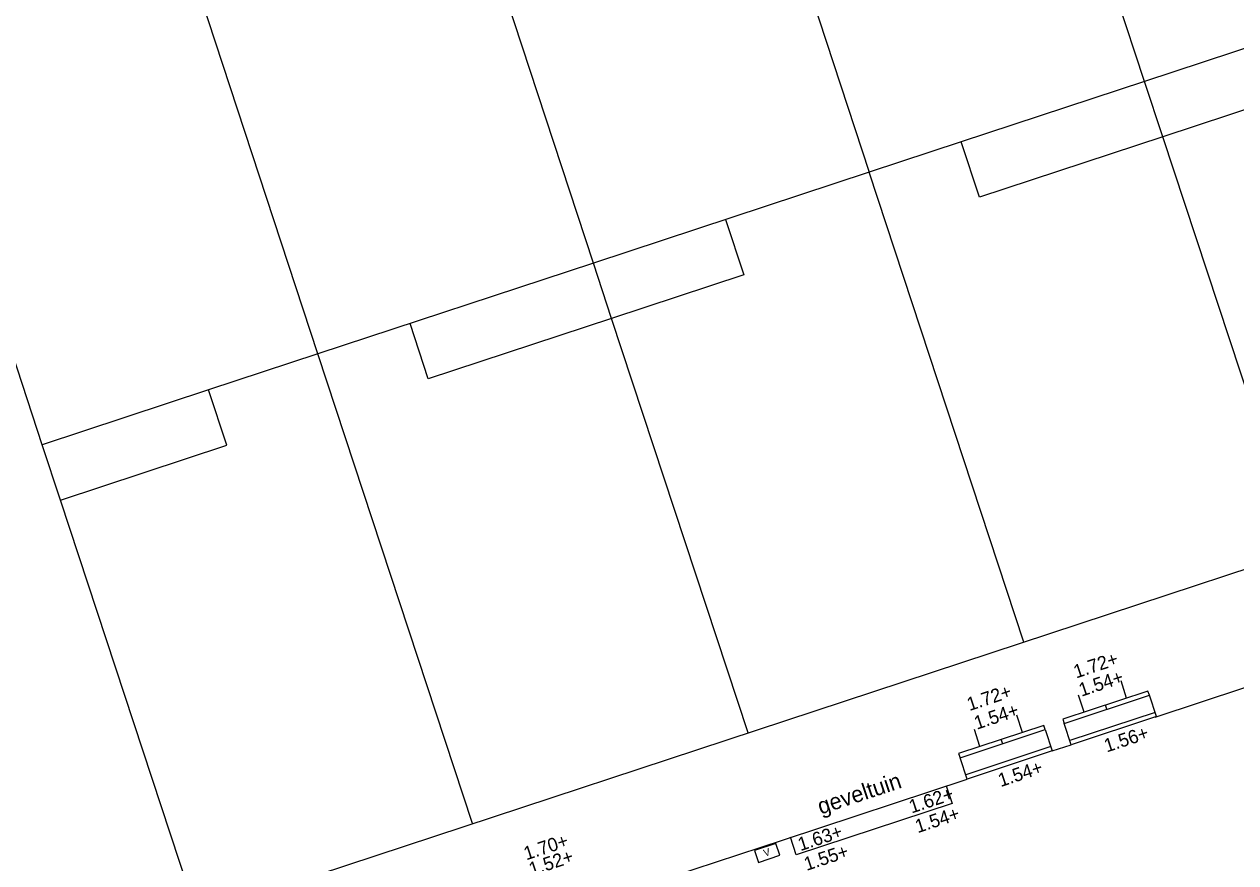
# Model space of a CAD drawing. Extents: x 122462 to 123306, y 485548 to 486417.
# Drawn here: x 122803.07 to 122830.05, y 486197.04 to 486215.71 of the extents above; entities that cross this region are included whole.
import ezdxf

# ---------------------------------------------------------------- set-up
doc = ezdxf.new("R2010")
doc.units = 0
for name, color, linetype in [('B-WE-AL-T25', 7, 'Continuous'), ('B-WE-AL-WERKGRENS-G', 7, 'Continuous'), ('B-WE-KL-DATA_TELECOM_KAST-S', 7, 'Continuous'), ('B-WE-OG-BEBOUWING_PORTIEK1-G', 7, 'Continuous'), ('B-WE-OG-BEBOUWING_TRAP-G', 7, 'Continuous'), ('B-WE-OG-HOOGTEPUNT-S', 7, 'Continuous'), ('B-WE-OG-TOPOKAART-G', 7, 'Continuous'), ('Level 1', 7, 'Continuous'), ('Level 19', 7, 'Continuous'), ('Level 4', 7, 'Continuous'), ('N-WE-AL-T25', 7, 'Continuous'), ('V opsluitband 100x200 mm', 7, 'Continuous')]:
    doc.layers.add(name, color=color, linetype=linetype)

msp = doc.modelspace()

# ---------------------------------------------------------------- linework, layer by layer
at = {"layer": 'B-WE-AL-WERKGRENS-G'}
msp.add_lwpolyline([(122857.632, 486078.279), (122830.484, 486160.606), (122900.937, 486183.81), (122887.855, 486222.555), (122665.445, 486149.273), (122678.196, 486110.449), (122807.072, 486152.895), (122835.324, 486068.154)], dxfattribs=at)
at = {"layer": 'B-WE-KL-DATA_TELECOM_KAST-S'}
msp.add_lwpolyline([(122819.805, 486197.469), (122819.33, 486197.312), (122819.418, 486197.046), (122819.893, 486197.203)], close=True, dxfattribs=at)
at = {"layer": 'B-WE-OG-BEBOUWING_PORTIEK1-G'}
for p, q in [((122827.62, 486200.706), (122827.495, 486201.085)), ((122826.671, 486200.392), (122826.545, 486200.772)), ((122827.177, 486200.454), (122827.146, 486200.549)), ((122825.303, 486199.941), (122825.177, 486200.321)), ((122824.353, 486199.627), (122824.228, 486200.007)), ((122824.859, 486199.689), (122824.828, 486199.784))]:
    msp.add_line(p, q, dxfattribs=at)
for points in [[(122826.227, 486200.141), (122828.127, 486200.767), (122828.095, 486200.862), (122826.196, 486200.236)], [(122823.909, 486199.376), (122825.809, 486200.002), (122825.777, 486200.097), (122823.878, 486199.471)]]:
    msp.add_lwpolyline(points, close=True, dxfattribs=at)
at = {"layer": 'B-WE-OG-BEBOUWING_TRAP-G'}
for points in [[(122828.252, 486200.387), (122826.353, 486199.761)], [(122828.283, 486200.292), (122826.384, 486199.666)], [(122825.934, 486199.623), (122824.035, 486198.996)], [(122825.965, 486199.528), (122824.066, 486198.901)]]:
    msp.add_lwpolyline(points, dxfattribs=at)
at = {"layer": 'B-WE-OG-TOPOKAART-G'}
for p, q in [((122828.283, 486200.292), (122828.127, 486200.767)), ((122824.066, 486198.901), (122823.909, 486199.376))]:
    msp.add_line(p, q, dxfattribs=at)
for points in [[(122828.254, 486200.283), (122832.249, 486201.601), (122836.308, 486202.94)], [(122825.809, 486200.002), (122825.965, 486199.528), (122826.384, 486199.666), (122826.227, 486200.141)], [(122815.999, 486196.239), (122819.975, 486197.551), (122824.066, 486198.901)]]:
    msp.add_lwpolyline(points, dxfattribs=at)
at = {"layer": 'Level 1'}
for p, q in [((122803.468, 486206.346), (122800.365, 486215.793)), ((122830.965, 486215.406), (122828.02, 486214.436)), ((122828.02, 486214.436), (122823.936, 486213.091)), ((122823.936, 486213.091), (122821.882, 486212.414)), ((122821.882, 486212.414), (122815.744, 486210.392)), ((122815.744, 486210.392), (122809.606, 486208.369)), ((122809.606, 486208.369), (122807.173, 486207.567)), ((122807.173, 486207.567), (122803.468, 486206.346))]:
    msp.add_line(p, q, dxfattribs=at)
at = {"layer": 'Level 19'}
for p, q in [((122818.88, 486221.575), (122821.882, 486212.414)), ((122828.02, 486214.436), (122825.688, 486221.461)), ((122815.744, 486210.392), (122812.708, 486219.648)), ((122809.606, 486208.369), (122806.537, 486217.721))]:
    msp.add_line(p, q, dxfattribs=at)
at = {"layer": 'Level 4'}
for p, q in [((122828.426, 486213.204), (122828.02, 486214.436)), ((122831.467, 486203.975), (122828.426, 486213.204)), ((122825.329, 486201.953), (122821.882, 486212.414)), ((122816.15, 486209.159), (122815.744, 486210.392)), ((122819.191, 486199.931), (122816.15, 486209.159)), ((122813.053, 486197.908), (122809.606, 486208.369)), ((122803.874, 486205.113), (122803.468, 486206.346)), ((122806.915, 486195.886), (122803.874, 486205.113))]:
    msp.add_line(p, q, dxfattribs=at)
at = {"layer": 'N-WE-AL-T25'}
msp.add_line((122807.173, 486207.567), (122807.173, 486207.568), dxfattribs=at)
for points in [[(122830.965, 486215.406), (122831.371, 486214.174), (122828.426, 486213.204)], [(122828.426, 486213.204), (122824.342, 486211.858), (122823.936, 486213.091)], [(122818.689, 486211.362), (122819.095, 486210.129), (122816.15, 486209.159)], [(122816.15, 486209.159), (122812.067, 486207.813), (122811.661, 486209.046)], [(122803.874, 486205.113), (122807.579, 486206.334), (122807.173, 486207.567)]]:
    msp.add_lwpolyline(points, dxfattribs=at)
at = {"layer": 'V opsluitband 100x200 mm'}
msp.add_lwpolyline([(122823.603, 486198.747), (122823.731, 486198.356), (122820.26, 486197.211), (122820.132, 486197.604)], dxfattribs=at)

# ---------------------------------------------------------------- texts
at = {"layer": 'B-WE-AL-T25'}
msp.add_text('geveltuin', height=0.36, rotation=18.3134, dxfattribs=at).set_placement((122820.807, 486198.108))
at = {"layer": 'B-WE-KL-DATA_TELECOM_KAST-S'}
msp.add_text('V', height=0.16, rotation=18.2611, dxfattribs=at).set_placement((122819.563, 486197.17))
at = {"layer": 'B-WE-OG-HOOGTEPUNT-S'}
for s, p in [('1.72+', (122826.496, 486201.14)), ('1.54+', (122826.613, 486200.734)), ('1.72+', (122824.121, 486200.414)), ('1.54+', (122824.282, 486199.999)), ('1.56+', (122827.176, 486199.492)), ('1.54+', (122824.815, 486198.722)), ('1.62+', (122822.831, 486198.133)), ('1.54+', (122822.967, 486197.694)), ('1.63+', (122820.356, 486197.294)), ('1.70+', (122814.25, 486197.09)), ('1.52+', (122814.365, 486196.741)), ('1.55+', (122820.492, 486196.855))]:
    msp.add_text(s, height=0.3, rotation=18.2611, dxfattribs=at).set_placement(p)

doc.saveas('drawing.dxf')
